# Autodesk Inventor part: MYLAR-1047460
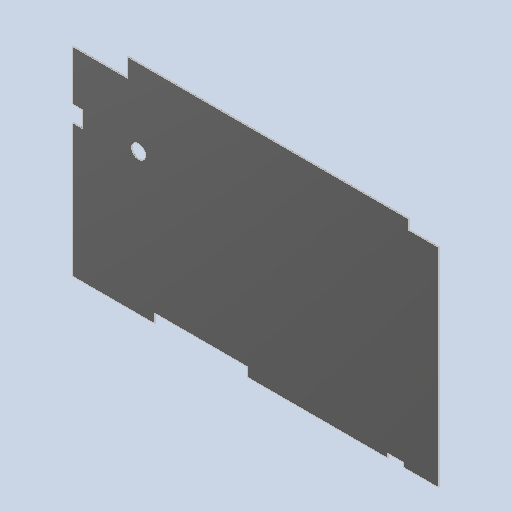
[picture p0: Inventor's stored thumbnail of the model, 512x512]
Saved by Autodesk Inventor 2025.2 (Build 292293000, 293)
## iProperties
Created: 2025-04
Part Number: MYLAR-1047460
Material: Generic
Description: NOT SPECIFIED
Document SubType Name: Modeling
Designer: BennF
Density: 1 g/cm^3
Appearance: Default
Author: BennF
Revision Number: 3LAST_VERSION
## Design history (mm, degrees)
feature "Base1"
body "Solid1"
